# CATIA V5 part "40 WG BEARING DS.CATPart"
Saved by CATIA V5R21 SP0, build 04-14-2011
Part number: 40 WG BEARING DS
Revision: ANY
Definition: UNKNOWN
Nomenclature: 40 WG BEARING DS
Source: Unknown
Bounding box of the stored display mesh (mm): x -7.445 to 7.445, y -49 to 49, z -49 to 49
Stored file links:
  C:\Users\MIRCEA\Desktop\PRRO\CATIAV5\40 WG BEARING DS.CATPart
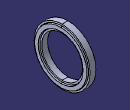
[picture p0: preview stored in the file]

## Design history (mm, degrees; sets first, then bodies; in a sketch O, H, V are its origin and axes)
Body1 "Revolve1" (main body)
  Solid1: solid without history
